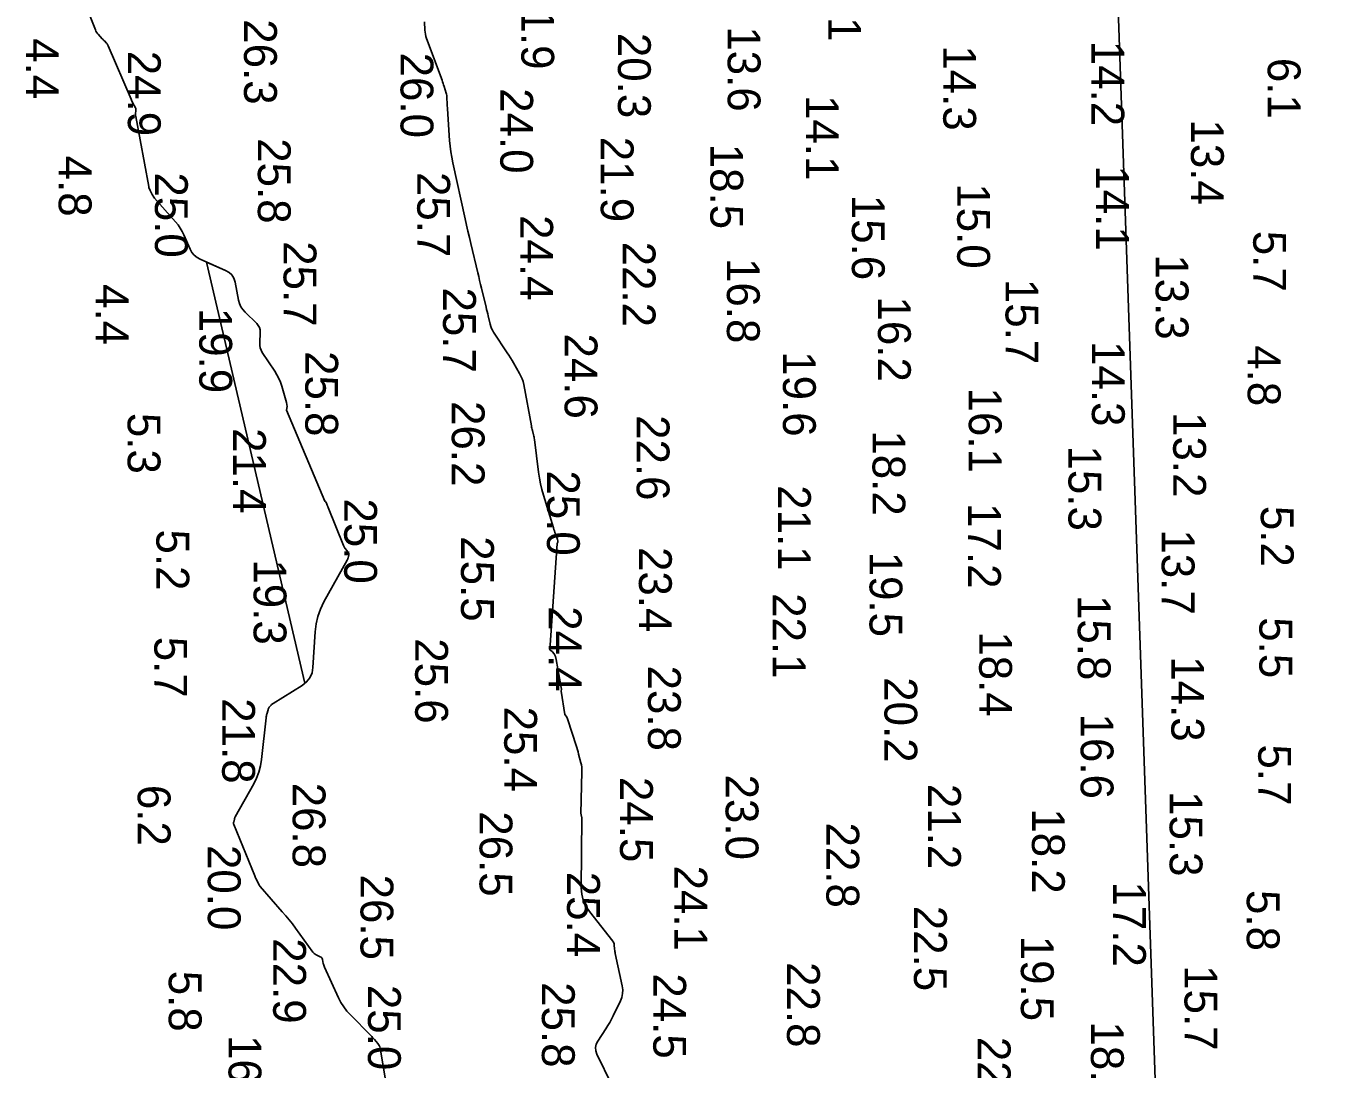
# Model space of a CAD drawing. Extents: x 1178573 to 1187098, y 693282 to 751751.
# Drawn here: x 1183662.5 to 1184157.7, y 750219.8 to 750617.3 of the extents above; entities that cross this region are included whole.
import ezdxf

# ---------------------------------------------------------------- set-up
doc = ezdxf.new("R2010")
doc.units = 0
for name, color, linetype in [('G-ANNO-PATT', 7, 'Continuous'), ('V-HYDS-MAJR', 7, 'Continuous'), ('V-HYDS-SOUN', 7, 'Continuous')]:
    doc.layers.add(name, color=color, linetype=linetype)

msp = doc.modelspace()

# ---------------------------------------------------------------- linework, layer by layer
at = {"layer": 'G-ANNO-PATT'}
msp.add_line((1183731.24, 750527.36), (1183768.72, 750366.84), dxfattribs=at)
for points in [[(1184123.8, 748210.03), (1184157.66, 748330.07), (1184109.72, 749719.65), (1184061.79, 751109.23), (1184061.85, 751109.87)], [(1183814.22, 750618.92), (1183814.4, 750615.71), (1183814.47, 750614.91), (1183814.61, 750614.13), (1183814.8, 750613.35), (1183815.05, 750612.59), (1183820.94, 750596.59), (1183821.15, 750596.02), (1183821.35, 750595.44), (1183821.54, 750594.87), (1183821.72, 750594.29), (1183822.5, 750591.76), (1183822.63, 750591.28), (1183822.73, 750590.79), (1183822.8, 750590.29), (1183822.83, 750589.79), (1183822.9, 750587.77), (1183822.92, 750587.27), (1183822.94, 750586.76), (1183822.97, 750586.26), (1183823, 750585.75), (1183823.83, 750573.72), (1183824.02, 750571.55), (1183824.29, 750569.4), (1183824.64, 750567.25), (1183825.07, 750565.12), (1183829.77, 750543.78), (1183830.3, 750541.43), (1183830.83, 750539.07), (1183831.37, 750536.72), (1183831.92, 750534.38), (1183834.55, 750523.26), (1183834.91, 750521.78), (1183835.26, 750520.3), (1183835.62, 750518.82), (1183835.98, 750517.35), (1183837.75, 750510.1), (1183837.94, 750509.29), (1183838.14, 750508.48), (1183838.33, 750507.67), (1183838.52, 750506.86), (1183839.29, 750503.63), (1183839.52, 750502.84), (1183839.81, 750502.07), (1183840.17, 750501.33), (1183840.59, 750500.63), (1183845.76, 750492.81), (1183846.38, 750491.85), (1183847, 750490.88), (1183847.6, 750489.89), (1183848.18, 750488.9), (1183850.49, 750484.92), (1183851.02, 750483.91), (1183851.46, 750482.86), (1183851.81, 750481.78), (1183852.07, 750480.67), (1183854.99, 750464.88), (1183855.08, 750464.45), (1183855.17, 750464.02), (1183855.27, 750463.59), (1183855.38, 750463.17), (1183855.82, 750461.46), (1183855.92, 750461.03), (1183856.01, 750460.6), (1183856.09, 750460.17), (1183856.15, 750459.74), (1183857.73, 750447.23), (1183858.05, 750445.01), (1183858.48, 750442.81), (1183858.99, 750440.64), (1183859.6, 750438.48), (1183863.41, 750426), (1183863.59, 750425.44), (1183863.77, 750424.88), (1183863.96, 750424.33), (1183864.15, 750423.78), (1183864.94, 750421.58), (1183865.06, 750421.05), (1183865.02, 750420.55), (1183864.82, 750420.1), (1183862.01, 750379.61), (1183862.92, 750378.88), (1183863.63, 750378.01), (1183864.14, 750377.02), (1183864.45, 750375.9), (1183866.33, 750365.24), (1183866.39, 750364.55), (1183866.34, 750363.88), (1183867.74, 750354.98), (1183868.19, 750354.35), (1183868.56, 750353.67), (1183868.84, 750352.94), (1183872.02, 750343.17), (1183872.28, 750342.35), (1183872.53, 750341.52), (1183872.76, 750340.69), (1183872.98, 750339.86), (1183873.83, 750336.52), (1183874.02, 750335.69), (1183874.14, 750334.84), (1183874.21, 750333.99), (1183874.22, 750333.13), (1183873.86, 750317.23), (1183873.86, 750317.08), (1183873.88, 750316.94), (1183873.9, 750316.8), (1183873.93, 750316.66), (1183874.1, 750316.11), (1183874.13, 750315.97), (1183874.16, 750315.83), (1183874.17, 750315.69), (1183874.18, 750315.55), (1183873.96, 750288.93), (1183874.14, 750286.46), (1183874.71, 750284.13), (1183875.69, 750281.94), (1183877.06, 750279.88), (1183885.95, 750268.57), (1183886.18, 750268.24), (1183886.36, 750267.88), (1183886.48, 750267.5), (1183886.54, 750267.1), (1183886.7, 750265.45), (1183886.75, 750265.03), (1183886.8, 750264.62), (1183886.87, 750264.21), (1183886.95, 750263.81), (1183889.6, 750251.48), (1183889.79, 750250), (1183889.74, 750248.56), (1183889.44, 750247.15), (1183888.9, 750245.77), (1183886.13, 750240.11), (1183885.49, 750238.85), (1183884.81, 750237.61), (1183884.09, 750236.39), (1183883.34, 750235.19), (1183880.23, 750230.46), (1183879.63, 750229.26), (1183879.37, 750228.05), (1183879.47, 750226.81), (1183879.91, 750225.54), (1183885.58, 750213.82)], [(1183768.72, 750366.84), (1183769.36, 750367.34), (1183770.61, 750368.92), (1183771.42, 750370.77), (1183771.79, 750372.89), (1183772.65, 750386.49), (1183773, 750389.46), (1183773.67, 750392.33), (1183774.66, 750395.12), (1183775.96, 750397.81), (1183784.83, 750413.79), (1183784.94, 750413.99), (1183785.03, 750414.2), (1183785.11, 750414.42), (1183785.18, 750414.64), (1183785.45, 750415.68), (1183785.48, 750415.83), (1183785.48, 750415.97), (1183785.45, 750416.11), (1183785.39, 750416.24), (1183785.1, 750416.78), (1183785.02, 750416.92), (1183784.94, 750417.05), (1183784.86, 750417.17), (1183784.77, 750417.3), (1183783.96, 750418.37), (1183783.81, 750418.6), (1183783.66, 750418.83), (1183783.54, 750419.07), (1183783.43, 750419.32), (1183777.58, 750433.85), (1183777.49, 750434.05), (1183777.41, 750434.26), (1183777.32, 750434.47), (1183777.23, 750434.68), (1183776.88, 750435.5), (1183776.78, 750435.7), (1183776.66, 750435.88), (1183776.51, 750436.04), (1183776.34, 750436.18), (1183761.75, 750470.94), (1183761.89, 750472.34), (1183761.64, 750473.84), (1183759.87, 750480), (1183759.37, 750481.52), (1183758.76, 750482.99), (1183758.05, 750484.4), (1183757.22, 750485.76), (1183752.49, 750492.93), (1183752.02, 750493.78), (1183751.7, 750494.66), (1183751.52, 750495.59), (1183751.49, 750496.56), (1183751.66, 750500.51), (1183751.61, 750501.46), (1183751.38, 750502.34), (1183750.95, 750503.15), (1183750.34, 750503.88), (1183745.92, 750508.24), (1183745.04, 750509.24), (1183744.33, 750510.34), (1183743.8, 750511.54), (1183743.45, 750512.83), (1183742.09, 750519.7), (1183741.63, 750521.18), (1183740.88, 750522.41), (1183739.83, 750523.42), (1183738.49, 750524.18), (1183731.24, 750527.36)]]:
    msp.add_lwpolyline(points, dxfattribs=at)
at = {"layer": 'V-HYDS-MAJR'}
for points in [[(1183681.03, 750635.82), (1183688.94, 750615.81), (1183689.13, 750615.36), (1183689.37, 750614.94), (1183689.64, 750614.55), (1183689.95, 750614.17), (1183691.52, 750612.44), (1183691.72, 750612.22), (1183691.92, 750612.01), (1183692.12, 750611.79), (1183692.32, 750611.58), (1183693.15, 750610.75), (1183693.34, 750610.53), (1183693.51, 750610.3), (1183693.66, 750610.05), (1183693.79, 750609.79), (1183702.49, 750589.38), (1183702.66, 750588.99), (1183702.84, 750588.6), (1183703.02, 750588.22), (1183703.22, 750587.84), (1183704.14, 750586.05), (1183704.25, 750585.8), (1183704.32, 750585.55), (1183704.35, 750585.29), (1183704.34, 750585.02), (1183704.24, 750583.93), (1183704.22, 750583.66), (1183704.22, 750583.39), (1183704.24, 750583.12), (1183704.29, 750582.85), (1183709.22, 750556.11), (1183709.31, 750555.71), (1183709.43, 750555.32), (1183709.58, 750554.94), (1183709.76, 750554.56), (1183710.53, 750553.1), (1183710.73, 750552.74), (1183710.95, 750552.4), (1183711.19, 750552.07), (1183711.46, 750551.75), (1183719.45, 750542.62), (1183720.37, 750541.48), (1183721.2, 750540.28), (1183721.94, 750539.02), (1183722.58, 750537.69), (1183724.97, 750532.28), (1183725.66, 750531.02), (1183726.54, 750529.96), (1183727.61, 750529.08), (1183728.87, 750528.39), (1183738.49, 750524.18), (1183739.83, 750523.42), (1183740.88, 750522.41), (1183741.63, 750521.18), (1183742.09, 750519.7), (1183743.45, 750512.83), (1183743.8, 750511.54), (1183744.33, 750510.34), (1183745.04, 750509.24), (1183745.92, 750508.24), (1183750.34, 750503.88), (1183750.95, 750503.15), (1183751.38, 750502.34), (1183751.61, 750501.46), (1183751.66, 750500.51), (1183751.49, 750496.56), (1183751.52, 750495.59), (1183751.7, 750494.66), (1183752.02, 750493.78), (1183752.49, 750492.93), (1183757.22, 750485.76), (1183758.05, 750484.4), (1183758.76, 750482.99), (1183759.37, 750481.52), (1183759.87, 750480), (1183761.64, 750473.84), (1183761.89, 750472.34), (1183761.75, 750470.94), (1183776.34, 750436.18), (1183776.51, 750436.04), (1183776.66, 750435.88), (1183776.78, 750435.7), (1183776.88, 750435.5), (1183777.23, 750434.68), (1183777.32, 750434.47), (1183777.41, 750434.26), (1183777.49, 750434.05), (1183777.58, 750433.85), (1183783.43, 750419.32), (1183783.54, 750419.07), (1183783.66, 750418.83), (1183783.81, 750418.6), (1183783.96, 750418.37), (1183784.77, 750417.3), (1183784.86, 750417.17), (1183784.94, 750417.05), (1183785.02, 750416.92), (1183785.1, 750416.78), (1183785.39, 750416.24), (1183785.45, 750416.11), (1183785.48, 750415.97), (1183785.48, 750415.83), (1183785.45, 750415.68), (1183785.18, 750414.64), (1183785.11, 750414.42), (1183785.03, 750414.2), (1183784.94, 750413.99), (1183784.83, 750413.79), (1183775.96, 750397.81), (1183774.66, 750395.12), (1183773.67, 750392.33), (1183773, 750389.46), (1183772.65, 750386.49), (1183771.79, 750372.89), (1183771.42, 750370.77), (1183770.61, 750368.92), (1183769.36, 750367.34), (1183767.66, 750366.02), (1183756.61, 750359.18), (1183756.39, 750359.04), (1183756.18, 750358.87), (1183755.99, 750358.69), (1183755.82, 750358.49), (1183755.14, 750357.67), (1183754.98, 750357.46), (1183754.85, 750357.24), (1183754.74, 750357), (1183754.66, 750356.75), (1183754.19, 750355.12), (1183754.1, 750354.76), (1183754.02, 750354.4), (1183753.96, 750354.03), (1183753.91, 750353.67), (1183752.19, 750337.75), (1183751.8, 750335.32), (1183751.18, 750332.97), (1183750.32, 750330.69), (1183749.23, 750328.49), (1183742.17, 750315.91), (1183742.07, 750315.71), (1183741.98, 750315.51), (1183741.91, 750315.3), (1183741.85, 750315.09), (1183741.58, 750313.94), (1183741.57, 750313.86), (1183741.55, 750313.78), (1183741.55, 750313.7), (1183741.55, 750313.62), (1183741.56, 750313.3), (1183741.56, 750313.22), (1183741.57, 750313.15), (1183741.59, 750313.07), (1183741.62, 750312.99), (1183749.59, 750293.49), (1183749.75, 750293.12), (1183749.91, 750292.75), (1183750.08, 750292.38), (1183750.26, 750292.02), (1183751.31, 750289.94), (1183751.33, 750289.89), (1183751.35, 750289.84), (1183751.38, 750289.79), (1183751.4, 750289.74), (1183751.5, 750289.55), (1183751.53, 750289.51), (1183751.56, 750289.46), (1183751.59, 750289.42), (1183751.62, 750289.38), (1183760.1, 750279.76), (1183761.42, 750278.24), (1183762.69, 750276.68), (1183763.93, 750275.1), (1183765.13, 750273.49), (1183771.73, 750264.4), (1183771.99, 750264.08), (1183772.28, 750263.81), (1183772.61, 750263.57), (1183772.97, 750263.37), (1183774.55, 750262.64), (1183774.86, 750262.45), (1183775.1, 750262.22), (1183775.27, 750261.93), (1183775.38, 750261.58), (1183775.68, 750260.11), (1183775.76, 750259.75), (1183775.87, 750259.39), (1183775.99, 750259.04), (1183776.14, 750258.69), (1183781.53, 750246.96), (1183782.45, 750245.18), (1183783.5, 750243.5), (1183784.7, 750241.93), (1183786.04, 750240.45), (1183793.82, 750232.59), (1183794.17, 750232.23), (1183794.52, 750231.86), (1183794.86, 750231.49), (1183795.19, 750231.11), (1183796.5, 750229.59), (1183796.8, 750229.19), (1183797.03, 750228.77), (1183797.21, 750228.31), (1183797.33, 750227.83), (1183800.35, 750210.33)], [(1183885.58, 750213.82), (1183879.91, 750225.54), (1183879.47, 750226.81), (1183879.37, 750228.05), (1183879.63, 750229.26), (1183880.23, 750230.46), (1183883.34, 750235.19), (1183884.09, 750236.39), (1183884.81, 750237.61), (1183885.49, 750238.85), (1183886.13, 750240.11), (1183888.9, 750245.77), (1183889.44, 750247.15), (1183889.74, 750248.56), (1183889.79, 750250), (1183889.6, 750251.48), (1183886.95, 750263.81), (1183886.87, 750264.21), (1183886.8, 750264.62), (1183886.75, 750265.03), (1183886.7, 750265.45), (1183886.54, 750267.1), (1183886.48, 750267.5), (1183886.36, 750267.88), (1183886.18, 750268.24), (1183885.95, 750268.57), (1183877.06, 750279.88), (1183875.69, 750281.94), (1183874.71, 750284.13), (1183874.14, 750286.46), (1183873.96, 750288.93), (1183874.18, 750315.55), (1183874.17, 750315.69), (1183874.16, 750315.83), (1183874.13, 750315.97), (1183874.1, 750316.11), (1183873.93, 750316.66), (1183873.9, 750316.8), (1183873.88, 750316.94), (1183873.86, 750317.08), (1183873.86, 750317.23), (1183874.22, 750333.13), (1183874.21, 750333.99), (1183874.14, 750334.84), (1183874.02, 750335.69), (1183873.83, 750336.52), (1183872.98, 750339.86), (1183872.76, 750340.69), (1183872.53, 750341.52), (1183872.28, 750342.35), (1183872.02, 750343.17), (1183868.84, 750352.94), (1183868.56, 750353.67), (1183868.19, 750354.35), (1183867.74, 750354.98), (1183866.34, 750363.88), (1183866.39, 750364.55), (1183866.33, 750365.24), (1183864.45, 750375.9), (1183864.14, 750377.02), (1183863.63, 750378.01), (1183862.92, 750378.88), (1183862.01, 750379.61), (1183864.82, 750420.1), (1183865.02, 750420.55), (1183865.06, 750421.05), (1183864.94, 750421.58), (1183864.15, 750423.78), (1183863.96, 750424.33), (1183863.77, 750424.88), (1183863.59, 750425.44), (1183863.41, 750426), (1183859.6, 750438.48), (1183858.99, 750440.64), (1183858.48, 750442.81), (1183858.05, 750445.01), (1183857.73, 750447.23), (1183856.15, 750459.74), (1183856.09, 750460.17), (1183856.01, 750460.6), (1183855.92, 750461.03), (1183855.82, 750461.46), (1183855.38, 750463.17), (1183855.27, 750463.59), (1183855.17, 750464.02), (1183855.08, 750464.45), (1183854.99, 750464.88), (1183852.07, 750480.67), (1183851.81, 750481.78), (1183851.46, 750482.86), (1183851.02, 750483.91), (1183850.49, 750484.92), (1183848.18, 750488.9), (1183847.6, 750489.89), (1183847, 750490.88), (1183846.38, 750491.85), (1183845.76, 750492.81), (1183840.59, 750500.63), (1183840.17, 750501.33), (1183839.81, 750502.07), (1183839.52, 750502.84), (1183839.29, 750503.63), (1183838.52, 750506.86), (1183838.33, 750507.67), (1183838.14, 750508.48), (1183837.94, 750509.29), (1183837.75, 750510.1), (1183835.98, 750517.35), (1183835.62, 750518.82), (1183835.26, 750520.3), (1183834.91, 750521.78), (1183834.55, 750523.26), (1183831.92, 750534.38), (1183831.37, 750536.72), (1183830.83, 750539.07), (1183830.3, 750541.43), (1183829.77, 750543.78), (1183825.07, 750565.12), (1183824.64, 750567.25), (1183824.29, 750569.4), (1183824.02, 750571.55), (1183823.83, 750573.72), (1183823, 750585.75), (1183822.97, 750586.26), (1183822.94, 750586.76), (1183822.92, 750587.27), (1183822.9, 750587.77), (1183822.83, 750589.79), (1183822.8, 750590.29), (1183822.73, 750590.79), (1183822.63, 750591.28), (1183822.5, 750591.76), (1183821.72, 750594.29), (1183821.54, 750594.87), (1183821.35, 750595.44), (1183821.15, 750596.02), (1183820.94, 750596.59), (1183815.05, 750612.59), (1183814.8, 750613.35), (1183814.61, 750614.13), (1183814.47, 750614.91), (1183814.4, 750615.71), (1183814.22, 750618.92)]]:
    msp.add_lwpolyline(points, dxfattribs=at)

# ---------------------------------------------------------------- texts
at = {"layer": 'V-HYDS-SOUN'}
for s, p in [('15.1 ', (1183968.05, 750643.94)), ('21.9 ', (1183851.15, 750633.25)), ('26.3 ', (1183745.53, 750619.87)), ('20.3 ', (1183887.95, 750614.68)), ('13.6 ', (1183929.75, 750617.18)), ('4.4', (1183662.47, 750612.63)), ('14.3 ', (1184011.87, 750609.93)), ('14.2 ', (1184068.32, 750611.66)), ('24.9 ', (1183701.28, 750607.86)), ('26.0 ', (1183805.14, 750607.15)), ('6.1', (1184135.46, 750605.15)), ('24.0 ', (1183843.13, 750593.6)), ('14.1 ', (1183959.52, 750590.99)), ('13.4 ', (1184106.22, 750581.69)), ('25.8 ', (1183750.79, 750574.53)), ('21.9 ', (1183881.4, 750575.08)), ('18.5 ', (1183923.13, 750572.44)), ('4.8', (1183674.93, 750567.88)), ('25.0 ', (1183711.6, 750561.51)), ('25.7 ', (1183811.51, 750561.67)), ('14.1 ', (1184070.11, 750564.19)), ('15.0 ', (1184017.18, 750557.35)), ('15.6 ', (1183977.06, 750552.97)), ('24.4 ', (1183850.74, 750545.24)), ('5.7', (1184129.95, 750539.27)), ('25.7 ', (1183760.59, 750535.29)), ('22.2 ', (1183889.74, 750535.12)), ('13.3 ', (1184092.77, 750530.3)), ('16.8 ', (1183929.46, 750528.89)), ('4.4', (1183689.07, 750518.93)), ('15.7 ', (1184035.59, 750520.92)), ('25.7 ', (1183821.35, 750517.64)), ('19.9 ', (1183728.48, 750509.9)), ('16.2 ', (1183986.99, 750514.22)), ('24.6 ', (1183867.64, 750500.12)), ('14.3 ', (1184068.49, 750497.23)), ('4.8', (1184127.85, 750495.64)), ('25.8 ', (1183768.86, 750493.42)), ('19.6 ', (1183950.81, 750493.36)), ('16.1 ', (1184021.59, 750479.51)), ('5.3', (1183701.18, 750469.87)), ('26.2 ', (1183824.65, 750474.39)), ('13.2 ', (1184099.45, 750470.19)), ('22.6 ', (1183895.07, 750469.02)), ('21.4 ', (1183741.33, 750464.07)), ('18.2 ', (1183984.92, 750463.21)), ('15.3 ', (1184059.57, 750457.43)), ('25.0 ', (1183860.91, 750447.96)), ('21.1 ', (1183948.92, 750442.3)), ('25.0 ', (1183783.68, 750437.27)), ('17.2 ', (1184021.3, 750435.48)), ('5.2', (1184132.84, 750434.44)), ('5.2', (1183712.14, 750425.45)), ('25.5 ', (1183828.18, 750422.87)), ('13.7 ', (1184095.07, 750425.48)), ('23.4 ', (1183895.95, 750418.76)), ('19.5 ', (1183983.79, 750416.99)), ('19.3 ', (1183749.17, 750414.03)), ('22.1 ', (1183946.92, 750401.16)), ('24.4 ', (1183861.57, 750396.19)), ('15.8 ', (1184063.12, 750400.48)), ('5.5', (1184132.28, 750392)), ('18.4 ', (1184025.55, 750386.64)), ('5.7', (1183711.35, 750384.57)), ('25.6 ', (1183810.72, 750383.98)), ('14.3 ', (1184098.74, 750377.12)), ('23.8 ', (1183899.38, 750373.58)), ('20.2 ', (1183989.45, 750369.14)), ('21.8 ', (1183737.2, 750361.14)), ('25.4 ', (1183844.64, 750357.94)), ('16.6 ', (1184064.2, 750355.3)), ('5.7', (1184131.86, 750343.53)), ('24.5 ', (1183888.75, 750331.13)), ('23.0 ', (1183928.96, 750332.05)), ('6.2', (1183705.02, 750328.11)), ('26.8 ', (1183764.04, 750328.96)), ('21.2 ', (1184006.08, 750328.5)), ('15.3 ', (1184098.09, 750325.74)), ('26.5 ', (1183835.24, 750318.05)), ('18.2 ', (1184045.65, 750319.18)), ('22.8 ', (1183967.35, 750313.77)), ('20.0 ', (1183731.72, 750305.21)), ('24.1 ', (1183909.45, 750297.36)), ('26.5 ', (1183789.89, 750293.93)), ('25.4 ', (1183868.59, 750295.01)), ('17.2 ', (1184076.55, 750291.29)), ('5.8', (1184127.49, 750288.06)), ('22.5 ', (1184000.72, 750282.05)), ('22.9 ', (1183756.63, 750269.67)), ('19.5 ', (1184041.44, 750270.64)), ('5.8', (1183716.86, 750257.29)), ('22.8 ', (1183952.36, 750260.58)), ('15.7 ', (1184103.76, 750259.4)), ('25.0 ', (1183792.74, 750251.9)), ('25.8 ', (1183858.99, 750252.94)), ('24.5 ', (1183901.41, 750256.3)), ('18.2 ', (1184068.12, 750237.98)), ('16.4 ', (1183739.62, 750232.81)), ('22.1 ', (1184025, 750232.1))]:
    msp.add_text(s, height=12.5, rotation=270, dxfattribs=at).set_placement(p)

doc.saveas('drawing.dxf')
